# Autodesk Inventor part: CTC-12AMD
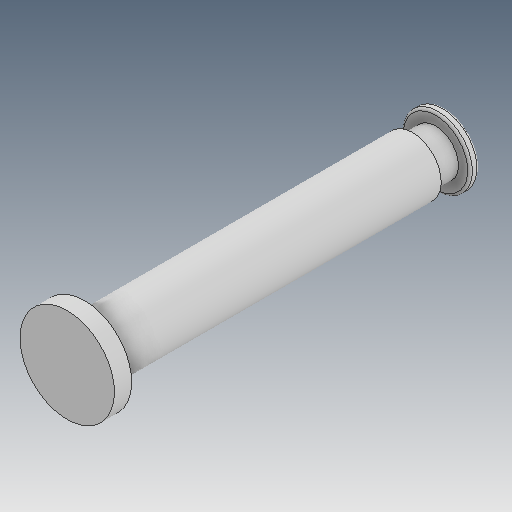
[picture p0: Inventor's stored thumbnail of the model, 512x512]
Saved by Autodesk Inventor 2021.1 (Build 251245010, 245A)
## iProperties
Created: 2010-01
Part Number: CTC-12AMD
Material: Ogólny
Document SubType Name: Modeling
Designer: user
Density: 1 g/cm^3
Appearance: Domyślna
Author: user
Revision Number: 1LAST_VERSION
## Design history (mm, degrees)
feature "Baza1"
node "Bryła1"
